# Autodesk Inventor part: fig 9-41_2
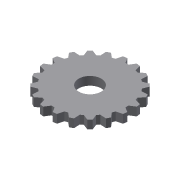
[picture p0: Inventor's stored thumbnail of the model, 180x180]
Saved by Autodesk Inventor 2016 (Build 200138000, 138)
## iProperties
Created: 2013-03
Part Number: fig 9-41_2
Material: Generic
Document SubType Name: Modeling
Designer: CADCIM
Density: 1 g/cm^3
Appearance: Default
Author: CADCIM
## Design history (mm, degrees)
sketch "Sketch1"
  geometry: C1 r 15 at (0, 0); C2 r 4 at (0, 0); 1 further point
  constraints: 2 centre point, 2 coincident
  dimensions: "d0" = 30 diameter of C1; "d2" = 8 diameter of C2
extrude "Extrusion1" new body sketch "Sketch1" distance "d3" = 3; taper "d4" = 0 deg
sketch "Sketch2"
  geometry: L1 (-1.675, 14.906)-(-0.536, 13.106); L2 (-0.536, 13.106)-(0.536, 13.106); L3 (0.536, 13.106)-(1.675, 14.906); L4 (0, 0)-(0, 16.254); C1 r 15 at (0, 0) reference; A1 r 15 centre (0, 0) between (1.675, 14.906) and (-1.675, 14.906); 2 further points
  constraints: 8 end point, 2 point on circle, 2 symmetric about line, 1 centre point, 1 coincident, 1 horizontal, 1 perpendicular
  dimensions: "d5" = 30 diameter of A1
extrude "Extrusion2" cut sketch "Sketch2" distance "d7" = 3; taper "d8" = 0 deg
body "Solid1"
pattern_circular "Circular Pattern1" dims angle "d10" = 360 deg
